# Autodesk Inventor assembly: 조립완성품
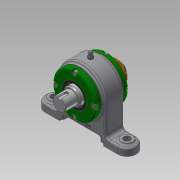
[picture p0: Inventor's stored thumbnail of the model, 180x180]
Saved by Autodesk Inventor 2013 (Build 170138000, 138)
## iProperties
Created: 2019-05
Part Number: 조립완성품
Document SubType Name: Assembly
Designer: Administrator
Author: Administrator
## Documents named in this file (13)
- C:\Users\Administrator\Desktop\490504V1002\조립완성품.iam
- C:\Users\Administrator\Desktop\490504V1002\본체.ipt
- C:\Users\Administrator\Desktop\490504V1002\490504V1002\개스킷.ipt
- C:\Users\Administrator\Desktop\490504V1002\490504V1002\그리스니플 M6.ipt
- 그리스니플  M6.ipt
- C:\Users\Administrator\Desktop\490504V1002\490504V1002\그리스니플개스킷.ipt
- C:\Users\Administrator\Desktop\490504V1002\490504V1002\베어링너트.ipt
- C:\Users\Administrator\Desktop\490504V1002\490504V1002\볼트 M4.ipt
- C:\Users\Administrator\Desktop\490504V1002\490504V1002\앵귤러 볼 베어링 7205.ipt
- C:\Users\Administrator\Desktop\490504V1002\490504V1002\오일 실 28 40 5 B.ipt
- C:\Users\Administrator\Desktop\490504V1002\490504V1002\축.ipt
- C:\Users\Administrator\Desktop\490504V1002\490504V1002\칼라.ipt
- C:\Users\Administrator\Desktop\490504V1002\490504V1002\커버.ipt
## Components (4 placed, 3 different names)
1. 개스킷:1
2. 그리스니플  M6:1 — 각도:2
3. 그리스니플개스킷:1
4. 개스킷:2
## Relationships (1: Angle 1)
- 각도:2 [Angle]: 그리스니플  M6:1
